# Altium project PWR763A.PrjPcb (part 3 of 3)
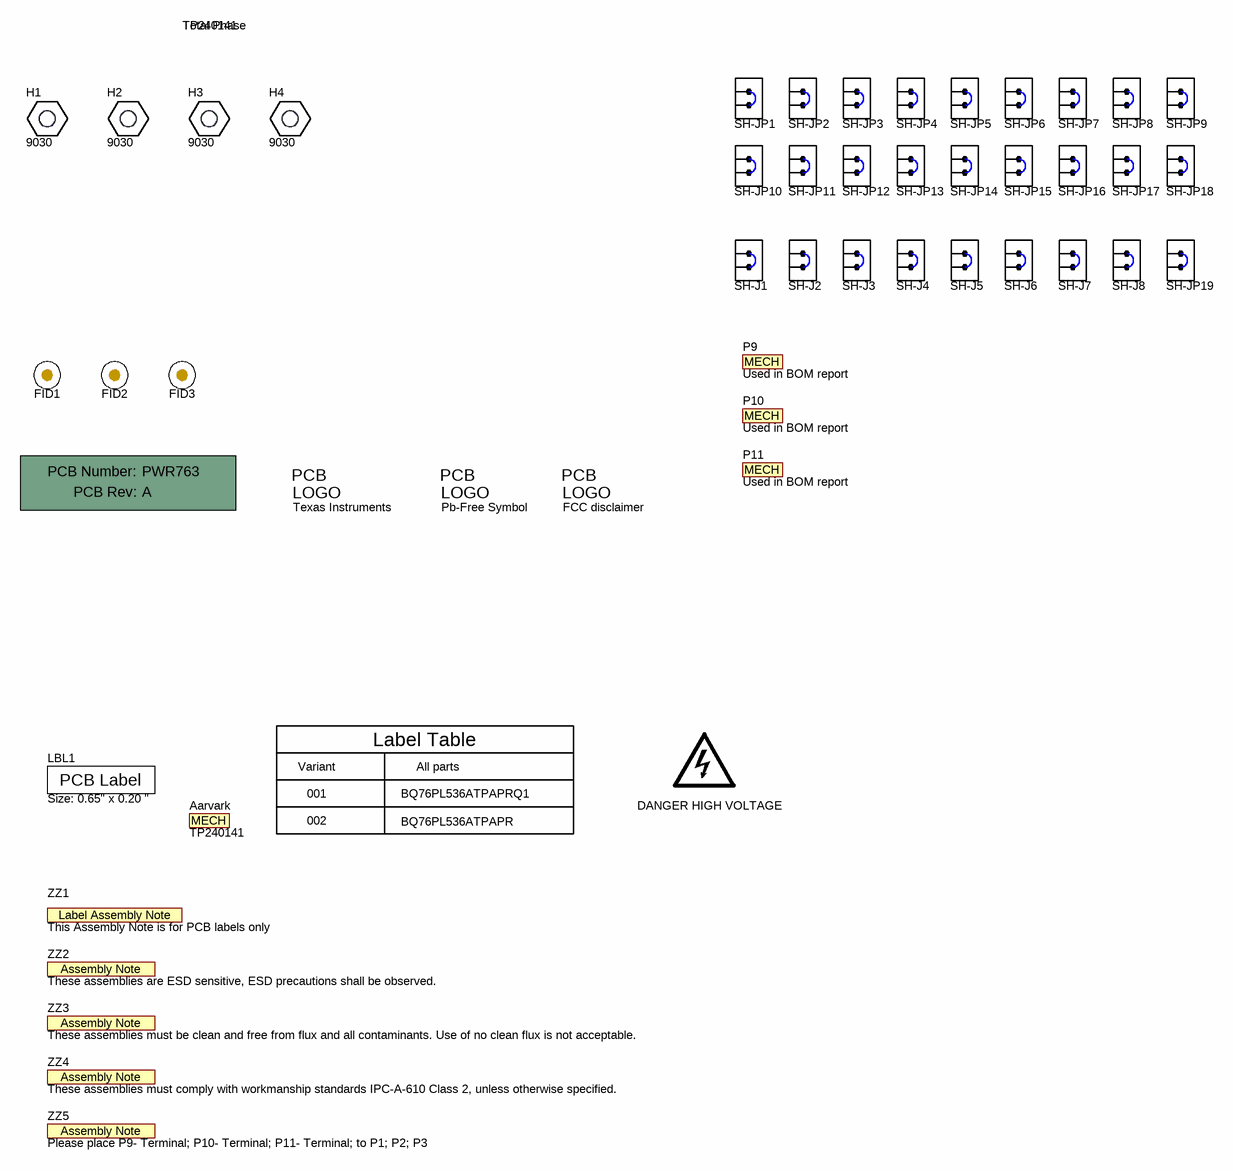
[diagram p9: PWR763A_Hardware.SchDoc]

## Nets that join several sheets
1-VC0: PWR763A_1 (23 pins), PWR763A_2 (48 pins), PWR763A_5 (18 pins)
2-VC0: PWR763A_1 (11 pins), PWR763A_3 (42 pins)
3-VC0: PWR763A_1 (10 pins), PWR763A_4 (42 pins)
AGND: PWR763A_1 (P5.2 P5.10 P6.6), PWR763A_5 (33 pins)
1-ALERT: PWR763A_2 (U1.38), PWR763A_5 (R189.1)
1-ALERT_N: PWR763A_1 (R39.1), PWR763A_2 (C37.1 U1.57)
1-ALERT_S: PWR763A_1 (R55.2 R59.2), PWR763A_2 (U1.23)
1-CELL1: PWR763A_1 (JP17.1 P1.6 R52.2), PWR763A_2 (10 pins)
1-CELL2: PWR763A_1 (JP16.1 P1.5 R51.2), PWR763A_2 (10 pins)
1-CELL3: PWR763A_1 (JP15.1 P1.4 R50.2), PWR763A_2 (10 pins)
1-CELL4: PWR763A_1 (JP14.1 P1.3 R49.2), PWR763A_2 (10 pins)
1-CELL5: PWR763A_1 (JP13.1 P1.2 R48.2), PWR763A_2 (10 pins)
1-CELL6: PWR763A_1 (P1.1 R37.1 R47.2 TP5.1), PWR763A_2 (6 pins)
1-CONV: PWR763A_1 (P7.1), PWR763A_2 (R83.1 U1.36), PWR763A_5 (R194.1)
1-CONV_N: PWR763A_1 (R42.1), PWR763A_2 (U1.59)
1-CONV_S: PWR763A_1 (C10.1 P8.4 R57.2), PWR763A_2 (U1.21)
1-CS_N: PWR763A_1 (R45.1), PWR763A_2 (R105.2 U1.52)
1-CS_S: PWR763A_1 (C13.1 P8.8 R64.2), PWR763A_2 (U1.29)
1-DRDY: PWR763A_2 (U1.37), PWR763A_5 (R196.1)
1-DRDY_N: PWR763A_1 (R38.1), PWR763A_2 (C38.1 U1.58)
1-DRDY_S: PWR763A_1 (R54.2 R58.2), PWR763A_2 (U1.22)
1-FAULT: PWR763A_2 (U1.39), PWR763A_5 (R188.1)
1-FAULT_N: PWR763A_1 (R40.1), PWR763A_2 (C36.1 U1.56)
1-FAULT_S: PWR763A_1 (R56.2 R60.2), PWR763A_2 (U1.24)
1-SCLK_N: PWR763A_1 (R43.1), PWR763A_2 (R103.2 U1.55)
1-SCLK_S: PWR763A_1 (C11.1 P8.7 R61.2), PWR763A_2 (U1.26)
1-SDI_N: PWR763A_1 (R44.1), PWR763A_2 (R104.2 U1.53)
1-SDI_S: PWR763A_1 (C12.1 P8.10 R63.2), PWR763A_2 (U1.28)
1-SDO_N: PWR763A_1 (R41.1), PWR763A_2 (C35.1 U1.54)
1-SDO_S: PWR763A_1 (R62.2 R65.2), PWR763A_2 (U1.27)
1-SPI-MISO: PWR763A_1 (P7.5), PWR763A_2 (U1.41), PWR763A_5 (R206.2)
1-SPI-MOSI: PWR763A_1 (P7.8), PWR763A_2 (R82.1 U1.42), PWR763A_5 (R201.2)
1-SPI-SCLK: PWR763A_1 (P7.7), PWR763A_2 (R80.1 U1.40), PWR763A_5 (R203.2)
1-SPI-SS: PWR763A_1 (P7.9), PWR763A_2 (R73.1), PWR763A_5 (R197.2)
1-VBAT: PWR763A_1 (R46.1), PWR763A_2 (10 pins)
2-ALERT_N: PWR763A_1 (R21.1), PWR763A_3 (C63.2 U2.57)
2-ALERT_S: PWR763A_1 (R39.2), PWR763A_3 (U2.23)
2-CELL1: PWR763A_1 (JP11.1 P2.6 R35.2), PWR763A_3 (10 pins)
2-CELL2: PWR763A_1 (JP10.1 P2.5 R34.2), PWR763A_3 (10 pins)
2-CELL3: PWR763A_1 (JP9.1 P2.4 R33.2), PWR763A_3 (10 pins)
2-CELL4: PWR763A_1 (JP8.1 P2.3 R32.2), PWR763A_3 (10 pins)
2-CELL5: PWR763A_1 (JP7.1 P2.2 R31.2), PWR763A_3 (10 pins)
2-CELL6: PWR763A_1 (P2.1 R20.1 R30.2 TP3.1), PWR763A_3 (6 pins)
2-CONV_N: PWR763A_1 (R25.1), PWR763A_3 (U2.59)
2-CONV_S: PWR763A_1 (R42.2), PWR763A_3 (C76.1 U2.21)
2-CS_N: PWR763A_1 (R28.1), PWR763A_3 (U2.52)
2-CS_S: PWR763A_1 (R45.2), PWR763A_3 (C75.1 U2.29)
2-DRDY_N: PWR763A_1 (R24.1), PWR763A_3 (C62.2 U2.58)
2-DRDY_S: PWR763A_1 (R38.2), PWR763A_3 (U2.22)
2-FAULT_N: PWR763A_1 (R22.1), PWR763A_3 (C64.2 U2.56)
2-FAULT_S: PWR763A_1 (R40.2), PWR763A_3 (U2.24)
2-SCLK_N: PWR763A_1 (R26.1), PWR763A_3 (U2.55)
2-SCLK_S: PWR763A_1 (R43.2), PWR763A_3 (C73.1 U2.26)
2-SDI_N: PWR763A_1 (R27.1), PWR763A_3 (U2.53)
2-SDI_S: PWR763A_1 (R44.2), PWR763A_3 (C74.1 U2.28)
2-SDO_N: PWR763A_1 (R23.1), PWR763A_3 (C65.2 U2.54)
2-SDO_S: PWR763A_1 (R41.2), PWR763A_3 (U2.27)
2-VBAT: PWR763A_1 (R29.1), PWR763A_3 (10 pins)
3-ALERT_N: PWR763A_1 (C2.2 P4.1 R4.1), PWR763A_4 (U3.57)
3-ALERT_S: PWR763A_1 (R21.2), PWR763A_4 (U3.23)
3-CELL1: PWR763A_1 (JP5.1 P3.6 R18.2), PWR763A_4 (10 pins)
3-CELL2: PWR763A_1 (JP4.1 P3.5 R17.2), PWR763A_4 (10 pins)
3-CELL3: PWR763A_1 (JP3.1 P3.4 R16.2), PWR763A_4 (10 pins)
3-CELL4: PWR763A_1 (JP2.1 P3.3 R15.2), PWR763A_4 (10 pins)
3-CELL5: PWR763A_1 (JP1.1 P3.2 R14.2), PWR763A_4 (10 pins)
3-CELL6: PWR763A_1 (P3.1 R13.2 TP1.1), PWR763A_4 (6 pins)
3-CONV_N: PWR763A_1 (R1.1 R2.1), PWR763A_4 (U3.59)
3-CONV_S: PWR763A_1 (R25.2), PWR763A_4 (C111.1 U3.21)
3-CS_N: PWR763A_1 (R9.1 R12.1), PWR763A_4 (U3.52)
3-CS_S: PWR763A_1 (R28.2), PWR763A_4 (C110.1 U3.29)
3-DRDY_N: PWR763A_1 (C1.2 P4.2 R3.1), PWR763A_4 (U3.58)
3-DRDY_S: PWR763A_1 (R24.2), PWR763A_4 (U3.22)
3-FAULT_N: PWR763A_1 (C3.2 P4.3 R5.1), PWR763A_4 (U3.56)
3-FAULT_S: PWR763A_1 (R22.2), PWR763A_4 (U3.24)
3-SCLK_N: PWR763A_1 (R6.1 R10.1), PWR763A_4 (U3.55)
3-SCLK_S: PWR763A_1 (R26.2), PWR763A_4 (C108.1 U3.26)
3-SDI_N: PWR763A_1 (R8.1 R11.1), PWR763A_4 (U3.53)
3-SDI_S: PWR763A_1 (R27.2), PWR763A_4 (C109.1 U3.28)
3-SDO_N: PWR763A_1 (C5.2 P4.9 R7.1), PWR763A_4 (U3.54)
3-SDO_S: PWR763A_1 (R23.2), PWR763A_4 (R177.2 U3.27)
3-VBAT: PWR763A_1 (15 pins), PWR763A_4 (6 pins)
3.3_SW: PWR763A_1 (P6.1), PWR763A_5 (17 pins)
5V_USB: PWR763A_1 (P5.4 P5.6), PWR763A_5 (C125.1 JP19.3 R210.1)
ALERT: PWR763A_1 (P6.3), PWR763A_5 (U4.13 U5.11)
CONV: PWR763A_1 (P6.5), PWR763A_5 (R204.2 U4.11 U5.9)
CS: PWR763A_1 (P5.9 P6.9), PWR763A_5 (R198.1 R207.2 U6.3)
DRDY: PWR763A_1 (P6.4), PWR763A_5 (U4.12 U5.10)
FAULT: PWR763A_1 (P6.2), PWR763A_5 (U4.14 U5.12)
GPIO0/I2C(SDA): PWR763A_1 (P5.3), PWR763A_5 (R192.1 U5.2)
GPIO1/I2C(SCL): PWR763A_1 (P5.1), PWR763A_5 (R191.1 U5.1)
SCLK: PWR763A_1 (P5.7 P6.10), PWR763A_5 (R200.1 R209.2 U6.5)
SIMO: PWR763A_1 (P5.8 P6.7), PWR763A_5 (R199.1 R208.2 U6.4)
SOMI: PWR763A_1 (P5.5 P6.8), PWR763A_5 (R205.1)

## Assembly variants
001 - BQ76PL536A-Q1: not fitted C1 C2 C3 C4 C5 C10 C11 C12 C13 C15 C16 C19 C24 C27 C30 C31 C32 C33 C49 C50 C53 C56 C61 C68 C70 C71 C72 C87 C88 C91 C94 C99 C102 C104 C105 C106 FID1 FID2 FID3 R1 R10 R11 R12 R20 R37 R54 R55 R56 R65 R94 R99 R103 R104 R105 R106 R140 R144 R177 R179 R184 R198 R199 R200 Z1 Z15 Z27
002 - BQ76PL536A: not fitted C1 C2 C3 C4 C5 C10 C11 C12 C13 C15 C16 C19 C24 C27 C30 C31 C32 C33 C49 C50 C53 C56 C61 C68 C70 C71 C72 C87 C88 C91 C94 C99 C102 C104 C105 C106 FID1 FID2 FID3 R1 R10 R11 R12 R20 R37 R54 R55 R56 R65 R94 R99 R103 R104 R105 R106 R140 R144 R177 R179 R184 R198 R199 R200 Z1 Z15 Z27; alternate parts U1 -> BQ76PL536APAPR, U2 -> BQ76PL536ATPAPRQ1, U3 -> BQ76PL536ATPAPRQ1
